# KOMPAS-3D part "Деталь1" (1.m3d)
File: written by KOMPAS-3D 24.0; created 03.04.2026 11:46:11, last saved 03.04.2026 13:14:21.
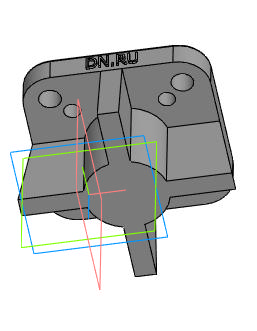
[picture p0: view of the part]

Document properties: Автор: R2D2; Полное имя файла: E:\Работа\Зайцев\Аксессуары для пневмоприводов\Ручной дублер DN.ru\MON1-250-T26-ISO Ручной дублер DN.ru\исходные материалы\1.m3d

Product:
- Body: Тело 2  | qty 1
    Масса: 0.720724
- Part/product: Деталь1
    Масса: 5.630796
    additional columns: Типовые

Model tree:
1. Операция без истории:1
2. Элемент выдавливания:1  (with: Грань.Операция без истории:1)
     Расстояние 1 = 0.5
3. Эскиз:1  (with: Ребро.Операция без истории:1)
4. Элемент выдавливания:2
     Расстояние 1 = 105; Расстояние 2 = 45
5. Эскиз:2  (with: Грань.Операция без истории:1, Ребро.Операция без истории:1)
6. Элемент выдавливания:3
     Расстояние 1 = 30
7. Эскиз:4  (with: Ребро.Элемент выдавливания:3)
8. Элемент выдавливания:5
     Расстояние 1 = 8
9. Массив по концентрической сетке:1  (with: Элемент выдавливания:5, Эскиз:4, Грань.Элемент выдавливания:3)  (4 pattern instances)
     Шаг 2 = 90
